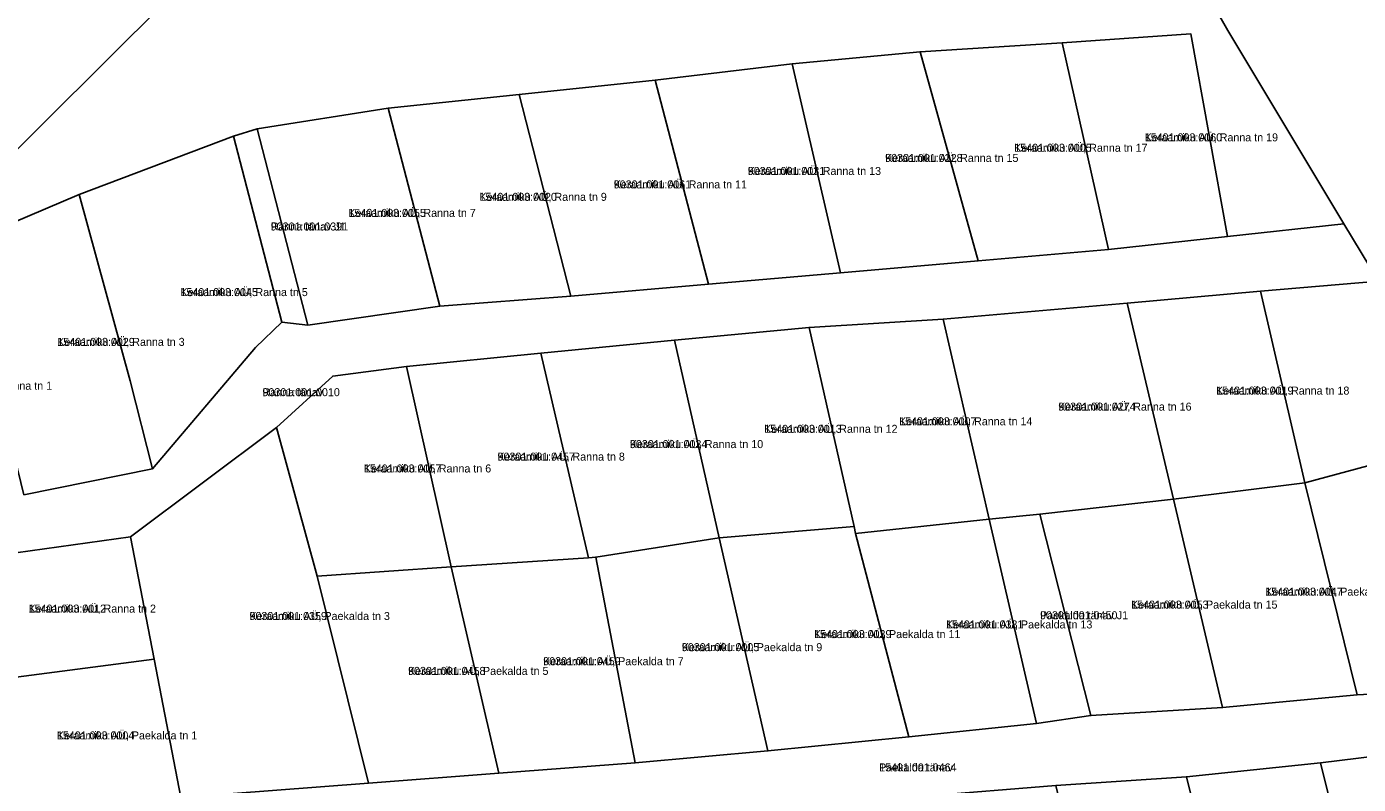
# Model space of a CAD drawing. Extents: x 634518 to 667988, y 6584667 to 6604739.
# Drawn here: x 661923.2 to 662172.8, y 6594785.3 to 6594927.4 of the extents above; entities that cross this region are included whole.
import ezdxf

# ---------------------------------------------------------------- set-up
doc = ezdxf.new("R2010")
doc.units = 0
for name, color, linetype in [('L_AADRESS', 7, 'Continuous'), ('PIIR', 7, 'Continuous'), ('TUNNUS', 7, 'Continuous')]:
    doc.layers.add(name, color=color, linetype=linetype)

msp = doc.modelspace()

# ---------------------------------------------------------------- linework, layer by layer
at = {"layer": 'PIIR'}
for points in [[(661973.17, 6595112.12), (662010.46, 6595162.78), (662037.55, 6595102.82), (662074.18, 6595056.38), (661903.85, 6594886.99), (661900.81, 6594883.94), (661884.44, 6594874.02), (661883.56, 6594873.54), (661881.68, 6594872.65), (661880.24, 6594872.33), (661878.61, 6594871.96), (661876.18, 6594871.39), (661873.75, 6594870.82), (661872.4, 6594870.5), (661868.9, 6594870.94), (661866.94, 6594873.21), (661862.98, 6594885.93), (661861.73, 6594890.79), (661860.89, 6594894.08), (661814.71, 6594910.83), (661813.41, 6594913.52), (661862.64, 6594966.78), (661876.64, 6594981)], [(662015.5, 6594914.68), (661990.96, 6594912.08), (661966.39, 6594908.23), (661961.99, 6594906.83), (661933.02, 6594895.92), (661911.1, 6594886.62), (661911.54, 6594885.03), (661885.54, 6594869.27), (661884.44, 6594874.02), (661900.81, 6594883.94), (661903.85, 6594886.99), (662074.18, 6595056.38), (662148.35, 6594926.69), (662170.09, 6594890.44), (662148.25, 6594888.05), (662141.41, 6594926.01), (662117.29, 6594924.33), (662090.66, 6594922.69), (662066.66, 6594920.41), (662040.97, 6594917.36)], [(662117.29, 6594924.33), (662141.41, 6594926.01), (662148.25, 6594888.05), (662125.96, 6594885.61)], [(662101.57, 6594883.49), (662090.66, 6594922.69), (662117.29, 6594924.33), (662125.96, 6594885.61)], [(662090.66, 6594922.69), (662101.57, 6594883.49), (662075.75, 6594881.25), (662066.66, 6594920.41)], [(662040.97, 6594917.36), (662066.66, 6594920.41), (662075.75, 6594881.25), (662050.97, 6594879.1)], [(662015.5, 6594914.68), (662040.97, 6594917.36), (662050.97, 6594879.1), (662025.19, 6594876.87)], [(662000.63, 6594875), (661990.96, 6594912.08), (662015.5, 6594914.68), (662025.19, 6594876.87)], [(661966.39, 6594908.23), (661990.96, 6594912.08), (662000.63, 6594875), (661975.89, 6594871.44)], [(661946.77, 6594844.49), (661942.59, 6594860.97), (661933.02, 6594895.92), (661961.99, 6594906.83), (661971.02, 6594871.96), (661966.08, 6594867.23)], [(661961.99, 6594906.83), (661966.39, 6594908.23), (661975.89, 6594871.44), (661971.02, 6594871.96)], [(661922.66, 6594839.62), (661911.54, 6594885.03), (661911.1, 6594886.62), (661933.02, 6594895.92), (661942.59, 6594860.97), (661946.77, 6594844.49)], [(662183.9, 6594867.42), (662194.07, 6594850.17), (662174.59, 6594845.03), (662162.77, 6594841.87), (662154.46, 6594877.77), (662176.57, 6594879.64)], [(662138.15, 6594838.79), (662129.5, 6594875.55), (662154.46, 6594877.77), (662162.77, 6594841.87)], [(662113.08, 6594835.99), (662103.61, 6594835.06), (662094.98, 6594872.56), (662129.5, 6594875.55), (662138.15, 6594838.79)], [(662044.63, 6594868.64), (662069.86, 6594871.01), (662078.27, 6594833.7), (662052.99, 6594831.53)], [(662078.56, 6594832.38), (662078.27, 6594833.7), (662069.86, 6594871.01), (662094.98, 6594872.56), (662103.61, 6594835.06)], [(662019.54, 6594866.16), (662044.63, 6594868.64), (662052.99, 6594831.53), (662029.87, 6594827.95), (662028.51, 6594827.83)], [(661994.38, 6594863.67), (662019.54, 6594866.16), (662028.51, 6594827.83), (662002.77, 6594826.13)], [(661970.02, 6594852.22), (661980.57, 6594861.87), (661994.38, 6594863.67), (662002.77, 6594826.13), (661977.67, 6594824.39)], [(661952.09, 6594782.9), (661947.1, 6594808.82), (661942.68, 6594831.72), (661970.02, 6594852.22), (661977.67, 6594824.39), (661987.24, 6594785.58)], [(662162.77, 6594841.87), (662174.59, 6594845.03), (662187.52, 6594838.46), (662202.25, 6594824.88), (662204.95, 6594820.68), (662209.52, 6594805.57), (662179.59, 6594802.52), (662172.57, 6594802.15)], [(662147.35, 6594799.74), (662138.15, 6594838.79), (662162.77, 6594841.87), (662172.57, 6594802.15)], [(662122.68, 6594798.22), (662113.08, 6594835.99), (662138.15, 6594838.79), (662147.35, 6594799.74)], [(662113.08, 6594835.99), (662122.68, 6594798.22), (662112.45, 6594796.74), (662103.61, 6594835.06)], [(662062.13, 6594791.6), (662052.99, 6594831.53), (662078.27, 6594833.7), (662078.56, 6594832.38), (662088.56, 6594794.22)], [(662088.56, 6594794.22), (662078.56, 6594832.38), (662103.61, 6594835.06), (662112.45, 6594796.74)], [(661905.34, 6594803.37), (661899.58, 6594825.77), (661942.68, 6594831.72), (661947.1, 6594808.82)], [(662037.26, 6594789.4), (662029.87, 6594827.95), (662052.99, 6594831.53), (662062.13, 6594791.6)], [(661987.24, 6594785.58), (661977.67, 6594824.39), (662002.77, 6594826.13), (662011.68, 6594787.45)], [(662002.77, 6594826.13), (662028.51, 6594827.83), (662029.87, 6594827.95), (662037.26, 6594789.4), (662011.68, 6594787.45)], [(661911.46, 6594778.72), (661905.34, 6594803.37), (661947.1, 6594808.82), (661952.09, 6594782.9)], [(662165.72, 6594789.4), (662190.16, 6594792.35), (662199.81, 6594755.95), (662174.73, 6594753.23)], [(662149.5, 6594750.24), (662140.59, 6594786.76), (662165.72, 6594789.4), (662174.73, 6594753.23), (662173.04, 6594753.04)], [(662125.18, 6594748.13), (662116.11, 6594785.1), (662140.59, 6594786.76), (662149.5, 6594750.24)]]:
    msp.add_lwpolyline(points, close=True, dxfattribs=at)
for points in [[(662090.94, 6595144.56), (662280.35, 6594886.74), (662407.03, 6594740.17), (662329.92, 6594651.1), (662328.61, 6594648.73), (662314.68, 6594669.18), (662307.84, 6594679.22), (662279.92, 6594718.15), (662278.97, 6594719.48), (662275.78, 6594723.93), (662273.25, 6594727.99), (662228.51, 6594796.96), (662221.81, 6594807.3), (662195.94, 6594847.18), (662194.07, 6594850.17), (662183.9, 6594867.42), (662176.57, 6594879.64), (662170.09, 6594890.44), (662148.35, 6594926.69), (662074.18, 6595056.38)], [(661922.66, 6594839.62), (661946.77, 6594844.49), (661966.08, 6594867.23), (661971.02, 6594871.96), (661975.89, 6594871.44), (662000.63, 6594875), (662025.19, 6594876.87), (662050.97, 6594879.1), (662075.75, 6594881.25), (662101.57, 6594883.49), (662125.96, 6594885.61), (662148.25, 6594888.05), (662170.09, 6594890.44), (662176.57, 6594879.64), (662154.46, 6594877.77), (662129.5, 6594875.55), (662094.98, 6594872.56), (662069.86, 6594871.01), (662044.63, 6594868.64), (662019.54, 6594866.16), (661994.38, 6594863.67), (661980.57, 6594861.87), (661970.02, 6594852.22), (661942.68, 6594831.72), (661899.58, 6594825.77)], [(662190.16, 6594792.35), (662165.72, 6594789.4), (662140.59, 6594786.76), (662116.11, 6594785.1), (662091.44, 6594783.13), (662066.07, 6594780.67), (662040.43, 6594778.16), (662016.57, 6594776.09), (661990.4, 6594774.76), (661965.51, 6594772.47), (661941.08, 6594770.36), (661916.96, 6594768.23), (661911.46, 6594778.72), (661952.09, 6594782.9), (661987.24, 6594785.58), (662011.68, 6594787.45), (662037.26, 6594789.4), (662062.13, 6594791.6), (662088.56, 6594794.22), (662112.45, 6594796.74), (662122.68, 6594798.22), (662147.35, 6594799.74), (662172.57, 6594802.15), (662179.59, 6594802.52)]]:
    msp.add_lwpolyline(points, dxfattribs=at)

# ---------------------------------------------------------------- texts
at = {"layer": 'L_AADRESS'}
for s, p in [('Keraamiku AÜ, Ranna tn 19', (662132.77, 6594905.88)), ('Keraamiku AÜ, Ranna tn 15', (662084.11, 6594902.02)), ('Keraamiku AÜ, Ranna tn 17', (662108.31, 6594903.93)), ('Keraamiku AÜ, Ranna tn 13', (662058.36, 6594899.58)), ('Keraamiku AÜ, Ranna tn 11', (662033.23, 6594897.06)), ('Keraamiku AÜ, Ranna tn 9', (662008.07, 6594894.73)), ('Keraamiku AÜ, Ranna tn 7', (661983.51, 6594891.72)), ('Ranna tänav J1', (661968.94, 6594889.17)), ('Keraamiku AÜ, Ranna tn 5', (661952.02, 6594876.87)), ('Keraamiku AÜ, Ranna tn 3', (661928.94, 6594867.54)), ('Keraamiku AÜ, Ranna tn 1', (661904.1, 6594859.32)), ('Ranna tänav', (661967.39, 6594858.11)), ('Keraamiku AÜ, Ranna tn 18', (662146.14, 6594858.41)), ('Keraamiku AÜ, Ranna tn 16', (662116.56, 6594855.4)), ('Keraamiku AÜ, Ranna tn 14', (662086.73, 6594852.65)), ('Keraamiku AÜ, Ranna tn 12', (662061.45, 6594851.24)), ('Keraamiku AÜ, Ranna tn 10', (662036.27, 6594848.38)), ('Keraamiku AÜ, Ranna tn 8', (662011.45, 6594846.03)), ('Keraamiku AÜ, Ranna tn 6', (661986.4, 6594843.81)), ('Keraamiku AÜ, Paekalda tn 17', (662155.36, 6594820.72)), ('Keraamiku AÜ, Ranna tn 2', (661923.56, 6594817.54)), ('Keraamiku AÜ, Paekalda tn 15', (662130.21, 6594818.29)), ('Keraamiku AÜ, Paekalda tn 3', (661964.96, 6594816.15)), ('Keraamiku AÜ, Paekalda tn 13', (662095.51, 6594814.57)), ('Paekalda tänav J1', (662113.14, 6594816.29)), ('Keraamiku AÜ, Paekalda tn 11', (662070.78, 6594812.76)), ('Keraamiku AÜ, Paekalda tn 9', (662046, 6594810.31)), ('Keraamiku AÜ, Paekalda tn 7', (662020.02, 6594807.68)), ('Keraamiku AÜ, Paekalda tn 5', (661994.68, 6594805.86)), ('Keraamiku AÜ, Paekalda tn 1', (661928.86, 6594793.77)), ('Paekalda tänav', (662082.98, 6594787.77))]:
    msp.add_text(s, height=1.5, dxfattribs=at).set_placement(p)
at = {"layer": 'TUNNUS'}
for s, p in [('15401:003:0060', (662132.77, 6594905.88)), ('90301:001:0228', (662084.11, 6594902.02)), ('15401:003:0005', (662108.31, 6594903.93)), ('90301:001:0031', (662058.36, 6594899.58)), ('90301:001:0061', (662033.23, 6594897.06)), ('15401:003:0020', (662008.07, 6594894.73)), ('15401:003:0055', (661983.51, 6594891.72)), ('90301:001:0391', (661968.94, 6594889.17)), ('15401:003:0045', (661952.02, 6594876.87)), ('15401:003:0029', (661928.94, 6594867.54)), ('90301:001:0010', (661967.39, 6594858.11)), ('15401:003:0019', (662146.14, 6594858.41)), ('90301:001:0274', (662116.56, 6594855.4)), ('15401:003:0007', (662086.73, 6594852.65)), ('15401:003:0013', (662061.45, 6594851.24)), ('90301:001:0034', (662036.27, 6594848.38)), ('90301:001:0457', (662011.45, 6594846.03)), ('15401:003:0057', (661986.4, 6594843.81)), ('15401:003:0047', (662155.36, 6594820.72)), ('15401:003:0012', (661923.56, 6594817.54)), ('15401:003:0053', (662130.21, 6594818.29)), ('90301:001:0359', (661964.96, 6594816.15)), ('15401:001:0381', (662095.51, 6594814.57)), ('90301:001:0450', (662113.14, 6594816.29)), ('15401:003:0039', (662070.78, 6594812.76)), ('90301:001:0005', (662046, 6594810.31)), ('90301:001:0459', (662020.02, 6594807.68)), ('90301:001:0458', (661994.68, 6594805.86)), ('15401:003:0004', (661928.86, 6594793.77)), ('15401:001:0464', (662082.98, 6594787.77))]:
    msp.add_text(s, height=1.5, dxfattribs=at).set_placement(p)

doc.saveas('drawing.dxf')
